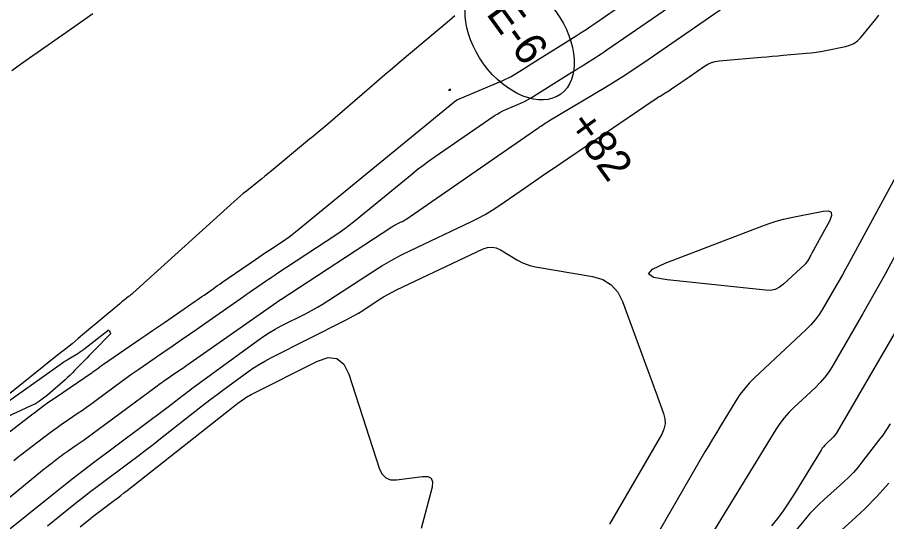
# Model space of a CAD drawing. Extents: x 1005228 to 1008882, y 1883389 to 1885754.
# Drawn here: x 1007802.3 to 1007972.9, y 1884979.6 to 1885078.7 of the extents above; entities that cross this region are included whole.
import ezdxf

# ---------------------------------------------------------------- set-up
doc = ezdxf.new("R2010")
doc.units = 0
for name, color, linetype in [('C-ANNO-NOTE', 7, 'Continuous'), ('R_Erosion', 7, 'Continuous'), ('S_BASELINE', 7, 'Continuous'), ('S_BRIDGE', 7, 'Continuous')]:
    doc.layers.add(name, color=color, linetype=linetype)

msp = doc.modelspace()

# ---------------------------------------------------------------- linework, layer by layer
at = {"layer": 'C-ANNO-NOTE'}
for points in [[(1007801.63, 1884991.64), (1007802.45, 1884992.3), (1007803.27, 1884992.95), (1007804.1, 1884993.6), (1007807.7, 1884996.36), (1007808.5, 1884996.97), (1007809.3, 1884997.56), (1007810.12, 1884998.14), (1007810.94, 1884998.72), (1007814.25, 1885000.98), (1007815.08, 1885001.55), (1007815.9, 1885002.13), (1007816.72, 1885002.71), (1007817.53, 1885003.31), (1007823.08, 1885007.41), (1007823.84, 1885007.97), (1007824.61, 1885008.52), (1007825.38, 1885009.06), (1007826.16, 1885009.6), (1007829.4, 1885011.84), (1007830.12, 1885012.33), (1007830.83, 1885012.82), (1007831.55, 1885013.31), (1007832.27, 1885013.81), (1007835.13, 1885015.78), (1007835.85, 1885016.27), (1007836.56, 1885016.77), (1007837.27, 1885017.26), (1007837.99, 1885017.76), (1007846.71, 1885023.88), (1007847.25, 1885024.26), (1007847.79, 1885024.63), (1007848.34, 1885025.01), (1007848.88, 1885025.38), (1007851.05, 1885026.88), (1007851.59, 1885027.25), (1007852.14, 1885027.62), (1007852.69, 1885027.99), (1007853.24, 1885028.35), (1007864.8, 1885035.96), (1007865.69, 1885036.57), (1007866.57, 1885037.2), (1007867.43, 1885037.85), (1007868.27, 1885038.52), (1007879.71, 1885047.91), (1007880.79, 1885048.78), (1007881.89, 1885049.62), (1007883, 1885050.44), (1007884.14, 1885051.24), (1007895.9, 1885059.33), (1007896.46, 1885059.69), (1007897.03, 1885060.02), (1007897.61, 1885060.32), (1007898.21, 1885060.6), (1007900.65, 1885061.62), (1007901.25, 1885061.89), (1007901.84, 1885062.18), (1007902.42, 1885062.5), (1007902.99, 1885062.83), (1007911.16, 1885067.91), (1007911.74, 1885068.26), (1007912.31, 1885068.62), (1007912.89, 1885068.98), (1007913.46, 1885069.35), (1007915.76, 1885070.79), (1007916.33, 1885071.16), (1007916.9, 1885071.53), (1007917.46, 1885071.9), (1007918.02, 1885072.29), (1007934.69, 1885083.85)], [(1007796, 1884980.5), (1007807.26, 1884989.72), (1007807.65, 1884990.05), (1007808.06, 1884990.37), (1007808.46, 1884990.69), (1007808.87, 1884991), (1007810.55, 1884992.3), (1007810.93, 1884992.59), (1007811.32, 1884992.87), (1007811.71, 1884993.15), (1007812.1, 1884993.42), (1007813.67, 1884994.5), (1007814.07, 1884994.77), (1007814.46, 1884995.05), (1007814.84, 1884995.32), (1007815.23, 1884995.61), (1007829.77, 1885006.34), (1007830.07, 1885006.56), (1007830.37, 1885006.78), (1007830.67, 1885006.99), (1007830.98, 1885007.2), (1007832.24, 1885008.07), (1007832.52, 1885008.27), (1007832.8, 1885008.46), (1007833.08, 1885008.65), (1007833.36, 1885008.84), (1007834.49, 1885009.62), (1007834.77, 1885009.81), (1007835.05, 1885010), (1007835.32, 1885010.2), (1007835.6, 1885010.39), (1007853.23, 1885022.75), (1007853.3, 1885022.79), (1007853.36, 1885022.84), (1007853.42, 1885022.88), (1007853.48, 1885022.92), (1007853.81, 1885023.17), (1007853.83, 1885023.18), (1007853.85, 1885023.19), (1007853.87, 1885023.2), (1007853.89, 1885023.21), (1007853.97, 1885023.25), (1007853.99, 1885023.26), (1007854.01, 1885023.28), (1007854.03, 1885023.29), (1007854.05, 1885023.3), (1007875.8, 1885037.55), (1007876.02, 1885037.69), (1007876.24, 1885037.82), (1007876.47, 1885037.94), (1007876.7, 1885038.05), (1007877.63, 1885038.5), (1007877.87, 1885038.61), (1007878.09, 1885038.74), (1007878.31, 1885038.87), (1007878.53, 1885039.01), (1007904.46, 1885056.92), (1007904.63, 1885057.05), (1007904.81, 1885057.17), (1007904.99, 1885057.29), (1007905.17, 1885057.41), (1007905.88, 1885057.9), (1007906.06, 1885058.02), (1007906.24, 1885058.13), (1007906.43, 1885058.25), (1007906.61, 1885058.36), (1007917.73, 1885064.98), (1007919.64, 1885066.14), (1007921.52, 1885067.32), (1007923.39, 1885068.54), (1007925.23, 1885069.79), (1007940.91, 1885080.59)], [(1007799.21, 1884976.95), (1007809.49, 1884985.2), (1007811.42, 1884986.73), (1007813.37, 1884988.25), (1007815.33, 1884989.76), (1007817.3, 1884991.24), (1007831.48, 1885001.85), (1007831.91, 1885002.17), (1007832.34, 1885002.5), (1007832.76, 1885002.83), (1007833.19, 1885003.16), (1007834.88, 1885004.5), (1007835.3, 1885004.83), (1007835.73, 1885005.16), (1007836.16, 1885005.48), (1007836.59, 1885005.8), (1007849.58, 1885015.31), (1007850.67, 1885016.07), (1007851.79, 1885016.79), (1007852.93, 1885017.46), (1007854.11, 1885018.08), (1007858.86, 1885020.47), (1007860.04, 1885021.09), (1007861.2, 1885021.74), (1007862.34, 1885022.42), (1007863.46, 1885023.13), (1007872.01, 1885028.73), (1007873.82, 1885029.88), (1007875.67, 1885030.95), (1007877.56, 1885031.97), (1007879.48, 1885032.92), (1007891.33, 1885038.52), (1007892.75, 1885039.23), (1007894.13, 1885039.99), (1007895.49, 1885040.81), (1007896.81, 1885041.68), (1007902.04, 1885045.29), (1007903.34, 1885046.19), (1007904.65, 1885047.09), (1007905.96, 1885047.99), (1007907.27, 1885048.88), (1007927.31, 1885062.51), (1007927.59, 1885062.69), (1007927.87, 1885062.88), (1007928.15, 1885063.05), (1007928.43, 1885063.22), (1007929.58, 1885063.9), (1007929.86, 1885064.08), (1007930.14, 1885064.25), (1007930.42, 1885064.44), (1007930.7, 1885064.62), (1007932.54, 1885065.89), (1007932.94, 1885066.17), (1007933.33, 1885066.44), (1007933.73, 1885066.72), (1007934.13, 1885066.99), (1007937.18, 1885069.12), (1007937.84, 1885069.52), (1007938.53, 1885069.83), (1007939.26, 1885070.04), (1007940.02, 1885070.15), (1007948.28, 1885070.86), (1007949.36, 1885070.96), (1007950.44, 1885071.05), (1007951.52, 1885071.14), (1007952.59, 1885071.24), (1007957.14, 1885071.63), (1007958.1, 1885071.73), (1007959.06, 1885071.85), (1007960.01, 1885072), (1007960.96, 1885072.18), (1007964.81, 1885072.94), (1007965.68, 1885073.19), (1007966.48, 1885073.57), (1007967.19, 1885074.09), (1007967.83, 1885074.74), (1007970.21, 1885077.62), (1007970.79, 1885078.34), (1007971.36, 1885079.08)], [(1007976.77, 1885051.28), (1007965.46, 1885030.39), (1007964.84, 1885029.26), (1007964.21, 1885028.12), (1007963.57, 1885027), (1007962.92, 1885025.88), (1007960.33, 1885021.4), (1007959.64, 1885020.31), (1007958.88, 1885019.28), (1007958.05, 1885018.31), (1007957.14, 1885017.39), (1007946.99, 1885007.87), (1007945.95, 1885006.84), (1007945, 1885005.74), (1007944.12, 1885004.58), (1007943.31, 1885003.36), (1007940.25, 1884998.36), (1007939.49, 1884997.11), (1007938.74, 1884995.85), (1007937.99, 1884994.59), (1007937.25, 1884993.32), (1007925.67, 1884973.25)], [(1007976.89, 1885036.2), (1007972.58, 1885028.25), (1007971.5, 1885026.27), (1007970.4, 1885024.29), (1007969.29, 1885022.33), (1007968.16, 1885020.37), (1007962.34, 1885010.33), (1007961.59, 1885009.14), (1007960.76, 1885008.01), (1007959.84, 1885006.94), (1007958.85, 1885005.94), (1007954.72, 1885002.07), (1007953.72, 1885001.07), (1007952.8, 1885000.01), (1007951.95, 1884998.89), (1007951.17, 1884997.72), (1007937.32, 1884975.1)], [(1007808.22, 1884978.83), (1007813.08, 1884982.73), (1007814.3, 1884983.7), (1007815.52, 1884984.66), (1007816.76, 1884985.6), (1007818, 1884986.54), (1007824.49, 1884991.4), (1007825.99, 1884992.52), (1007827.47, 1884993.66), (1007828.95, 1884994.8), (1007830.42, 1884995.96), (1007838.1, 1885002.01), (1007839.23, 1885002.9), (1007840.37, 1885003.77), (1007841.51, 1885004.64), (1007842.66, 1885005.49), (1007847.3, 1885008.88), (1007848.47, 1885009.7), (1007849.67, 1885010.47), (1007850.91, 1885011.19), (1007852.18, 1885011.87), (1007866.72, 1885019.19), (1007867.58, 1885019.64), (1007868.43, 1885020.11), (1007869.27, 1885020.61), (1007870.09, 1885021.13), (1007873.35, 1885023.27), (1007874.17, 1885023.79), (1007875.01, 1885024.28), (1007875.86, 1885024.74), (1007876.74, 1885025.17), (1007893.73, 1885033.2), (1007894.6, 1885033.5), (1007895.46, 1885033.57), (1007896.3, 1885033.42), (1007897.14, 1885033.03), (1007900.45, 1885031.02), (1007901.29, 1885030.56), (1007902.17, 1885030.19), (1007903.07, 1885029.9), (1007904.01, 1885029.69), (1007915.2, 1885027.77), (1007917.2, 1885027.18), (1007918.85, 1885026.17), (1007920.15, 1885024.73), (1007921.09, 1885022.86), (1007926.07, 1885009.3), (1007926.45, 1885008.25), (1007926.84, 1885007.2), (1007927.22, 1885006.15), (1007927.6, 1885005.09), (1007929.12, 1885000.89), (1007929.38, 1884999.85), (1007929.41, 1884998.83), (1007929.21, 1884997.83), (1007928.76, 1884996.85), (1007918.55, 1884979.16)], [(1007975.73, 1885018.88), (1007963.21, 1884997.29), (1007962.99, 1884996.95), (1007962.76, 1884996.63), (1007962.5, 1884996.33), (1007962.22, 1884996.05), (1007961.05, 1884994.95), (1007960.76, 1884994.66), (1007960.5, 1884994.36), (1007960.26, 1884994.05), (1007960.04, 1884993.71), (1007954.63, 1884984.87), (1007953.63, 1884983.31), (1007952.57, 1884981.78), (1007951.46, 1884980.29), (1007950.3, 1884978.84)], [(1007973.32, 1884987.22), (1007971.03, 1884984.63), (1007968.61, 1884982.15), (1007966.08, 1884979.77), (1007952.06, 1884967.19)]]:
    msp.add_lwpolyline(points, dxfattribs=at)
msp.add_lwpolyline([(1007958.12, 1885032.14), (1007958.01, 1885031.95), (1007957.91, 1885031.76), (1007957.8, 1885031.58), (1007957.36, 1885030.82), (1007957.24, 1885030.64), (1007957.12, 1885030.46), (1007956.98, 1885030.3), (1007956.82, 1885030.15), (1007952.68, 1885026.26), (1007951.9, 1885025.66), (1007951.05, 1885025.26), (1007950.14, 1885025.07), (1007949.16, 1885025.08), (1007929.86, 1885027.11), (1007927.17, 1885027.59), (1007926.2, 1885028.31), (1007926.95, 1885029.25), (1007929.43, 1885030.41), (1007948.42, 1885037.69), (1007949.83, 1885038.2), (1007951.25, 1885038.64), (1007952.69, 1885039.03), (1007954.15, 1885039.35), (1007960.42, 1885040.59), (1007961.46, 1885040.67), (1007962.02, 1885040.4), (1007962.11, 1885039.78), (1007961.73, 1885038.81), (1007958.22, 1885032.34)], close=True, dxfattribs=at)
at = {"layer": 'R_Erosion'}
msp.add_ellipse((1007900.9, 1885074.68), major_axis=(8.04, -11.09), ratio=0.638788, dxfattribs=at)
at = {"layer": 'S_BRIDGE'}
for points in [[(1007796.92, 1884994.32), (1007804.84, 1885000.42), (1007806.06, 1885001.34), (1007807.29, 1885002.25), (1007808.53, 1885003.14), (1007809.79, 1885004.01), (1007816.98, 1885008.93), (1007817.17, 1885009.06), (1007817.36, 1885009.19), (1007817.54, 1885009.33), (1007817.73, 1885009.46), (1007818.47, 1885010.01), (1007818.66, 1885010.15), (1007818.84, 1885010.28), (1007819.03, 1885010.41), (1007819.22, 1885010.54), (1007826.56, 1885015.6), (1007827.71, 1885016.39), (1007828.86, 1885017.18), (1007830.02, 1885017.98), (1007831.17, 1885018.77), (1007837.2, 1885022.92), (1007837.64, 1885023.22), (1007838.08, 1885023.53), (1007838.52, 1885023.84), (1007838.96, 1885024.14), (1007840.72, 1885025.37), (1007841.15, 1885025.68), (1007841.59, 1885025.99), (1007842.04, 1885026.29), (1007842.48, 1885026.6), (1007849.05, 1885031.13), (1007849.71, 1885031.58), (1007850.36, 1885032.02), (1007851.03, 1885032.47), (1007851.69, 1885032.91), (1007854.35, 1885034.66), (1007855, 1885035.1), (1007855.65, 1885035.56), (1007856.28, 1885036.04), (1007856.9, 1885036.54), (1007887.98, 1885062.04), (1007888.04, 1885062.09), (1007888.1, 1885062.14), (1007888.17, 1885062.18), (1007888.23, 1885062.23), (1007888.49, 1885062.41), (1007888.55, 1885062.45), (1007888.62, 1885062.49), (1007888.69, 1885062.52), (1007888.76, 1885062.55), (1007897.59, 1885066.28), (1007898.14, 1885066.52), (1007898.68, 1885066.79), (1007899.2, 1885067.07), (1007899.72, 1885067.38), (1007901.76, 1885068.65), (1007902.27, 1885068.96), (1007902.78, 1885069.28), (1007903.29, 1885069.6), (1007903.8, 1885069.92), (1007911.97, 1885075.06), (1007912.94, 1885075.68), (1007913.91, 1885076.32), (1007914.87, 1885076.96), (1007915.82, 1885077.61), (1007919.62, 1885080.25)], [(1007801.23, 1885068.22), (1007802.97, 1885069.5), (1007804.73, 1885070.76), (1007811.84, 1885075.71), (1007813.61, 1885076.95), (1007815.39, 1885078.18), (1007817.17, 1885079.42)], [(1007888.16, 1885078.95), (1007887.12, 1885078.07), (1007877.45, 1885069.93), (1007875.94, 1885068.66), (1007874.44, 1885067.38), (1007872.94, 1885066.09), (1007871.44, 1885064.8), (1007863.28, 1885057.71), (1007862.89, 1885057.38), (1007862.49, 1885057.04), (1007862.09, 1885056.71), (1007861.69, 1885056.39), (1007860.08, 1885055.09), (1007859.68, 1885054.76), (1007859.27, 1885054.43), (1007858.88, 1885054.1), (1007858.48, 1885053.77), (1007852.1, 1885048.45), (1007851.5, 1885047.95), (1007850.9, 1885047.46), (1007850.3, 1885046.97), (1007849.69, 1885046.49), (1007847.26, 1885044.56), (1007846.65, 1885044.07), (1007846.06, 1885043.57), (1007845.47, 1885043.07), (1007844.89, 1885042.55), (1007825.01, 1885024.54), (1007824.81, 1885024.35), (1007824.59, 1885024.17), (1007824.38, 1885024), (1007824.16, 1885023.83), (1007823.29, 1885023.15), (1007823.07, 1885022.98), (1007822.85, 1885022.8), (1007822.64, 1885022.63), (1007822.42, 1885022.45), (1007815.51, 1885016.63), (1007814.28, 1885015.61), (1007813.05, 1885014.59), (1007811.81, 1885013.58), (1007810.56, 1885012.58), (1007793.08, 1884998.57)], [(1007793.36, 1884998.21), (1007811.17, 1885010.81), (1007811.53, 1885011.07), (1007811.9, 1885011.31), (1007812.27, 1885011.55), (1007812.65, 1885011.78), (1007814.17, 1885012.69), (1007814.55, 1885012.93), (1007814.92, 1885013.17), (1007815.28, 1885013.43), (1007815.63, 1885013.7), (1007820.05, 1885017.18), (1007820.13, 1885017.22), (1007820.2, 1885017.23), (1007820.27, 1885017.2), (1007820.33, 1885017.13), (1007820.56, 1885016.77), (1007820.6, 1885016.68), (1007820.6, 1885016.6), (1007820.58, 1885016.51), (1007820.52, 1885016.44), (1007817.36, 1885013.2), (1007816.9, 1885012.72), (1007816.43, 1885012.24), (1007815.96, 1885011.76), (1007815.49, 1885011.28), (1007813.62, 1885009.36), (1007813.15, 1885008.89), (1007812.67, 1885008.42), (1007812.18, 1885007.96), (1007811.68, 1885007.52), (1007808.25, 1885004.5), (1007807.49, 1885003.88), (1007806.69, 1885003.32), (1007805.86, 1885002.81), (1007804.98, 1885002.36), (1007800.22, 1885000.14)], [(1007814.65, 1884978.64), (1007816.66, 1884980.26), (1007817.17, 1884980.66), (1007817.68, 1884981.06), (1007818.19, 1884981.45), (1007818.7, 1884981.84), (1007821.4, 1884983.86), (1007822.02, 1884984.32), (1007822.63, 1884984.79), (1007823.24, 1884985.27), (1007823.86, 1884985.75), (1007844.36, 1885001.94), (1007844.67, 1885002.18), (1007844.98, 1885002.42), (1007845.29, 1885002.65), (1007845.61, 1885002.88), (1007846.87, 1885003.8), (1007847.18, 1885004.03), (1007847.51, 1885004.24), (1007847.85, 1885004.43), (1007848.19, 1885004.62), (1007861.2, 1885011.17), (1007863.3, 1885011.87), (1007865.03, 1885011.68), (1007866.38, 1885010.59), (1007867.35, 1885008.6), (1007873.4, 1884989.98), (1007873.9, 1884988.94), (1007874.62, 1884988.24), (1007875.56, 1884987.88), (1007876.72, 1884987.88), (1007881.8, 1884988.54), (1007882.87, 1884988.54), (1007883.54, 1884988.18), (1007883.82, 1884987.46), (1007883.69, 1884986.4), (1007881.58, 1884978.29)], [(1007973.59, 1884998.84), (1007972.88, 1884997.71), (1007972.13, 1884996.62), (1007971.33, 1884995.55), (1007968.05, 1884991.3), (1007967.23, 1884990.28), (1007966.37, 1884989.31), (1007965.46, 1884988.37), (1007964.5, 1884987.47), (1007960.61, 1884983.98), (1007959.65, 1884983.09), (1007958.72, 1884982.16), (1007957.84, 1884981.21), (1007956.98, 1884980.22), (1007945.85, 1884966.84)]]:
    msp.add_lwpolyline(points, dxfattribs=at)
msp.add_lwpolyline([(1007887.32, 1885064.54), (1007887.32, 1885064.55), (1007887.33, 1885064.55), (1007887.33, 1885064.56), (1007887.32, 1885064.59), (1007887.32, 1885064.6), (1007887.32, 1885064.6), (1007887.31, 1885064.6), (1007887.31, 1885064.6), (1007886.96, 1885064.4), (1007886.95, 1885064.39), (1007886.95, 1885064.39), (1007886.96, 1885064.38), (1007886.97, 1885064.38), (1007887.03, 1885064.36), (1007887.04, 1885064.36), (1007887.05, 1885064.36), (1007887.05, 1885064.36), (1007887.06, 1885064.36), (1007887.09, 1885064.37), (1007887.1, 1885064.37), (1007887.11, 1885064.37), (1007887.11, 1885064.37), (1007887.12, 1885064.37), (1007887.32, 1885064.37), (1007887.34, 1885064.37), (1007887.35, 1885064.38), (1007887.35, 1885064.39), (1007887.35, 1885064.41), (1007887.29, 1885064.51), (1007887.29, 1885064.51), (1007887.29, 1885064.52), (1007887.29, 1885064.52), (1007887.3, 1885064.53), (1007887.32, 1885064.54)], close=True, dxfattribs=at)

# ---------------------------------------------------------------- texts
at = {"layer": 'R_Erosion'}
msp.add_text('E-6', height=6.25, rotation=305.9673, dxfattribs=at).set_placement((1007894.19, 1885079.39))
at = {"layer": 'S_BASELINE'}
msp.add_text('+82', height=6.25, rotation=305.9673, dxfattribs=at).set_placement((1007910.09, 1885057.48))

doc.saveas('drawing.dxf')
